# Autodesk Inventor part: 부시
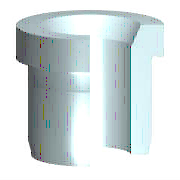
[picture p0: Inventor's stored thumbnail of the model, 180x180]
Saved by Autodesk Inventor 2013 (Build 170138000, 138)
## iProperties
IsCustomPart: 1
Created: 2009-02
Part Number: 부시
Material: 강, 연강
Description: 압력 맞춤 부시 - 머리 있는 유형
Document SubType Name: Modeling
Standard: ISO 4247
Designer: KYOUNG IL JANG
Standard Revision: 1판 1977-12-15
Standards Organization: ISO
Language: ko-KR
Size Designation: 15
Categories: <MemberInstance><Categories><Category DisplayName="기타 부품" InternalName="5aa15e00-363f-49f2-933f-16f664388e3f" Mnemonic="OTHER"><Category DisplayName="드릴 부싱" Int
Density: 7.86 g/cm^3
Mass: 62.5871 g
Surface Area: 38.4072 cm^2
Volume: 7.96273 cm^3
Author: KYOUNG IL JANG
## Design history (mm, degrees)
revolve "본체" stored, may be unused: angle "d12" = 90 deg
body "Solid1"
chamfer "모따기1" distance "d13" = 2 (= KAH); stored, may be unused: angle "d14" = 30 deg (= SEWI), second distance "d19" = 2 (= KAH)
chamfer "모따기2" distance "d15" = 1.5 (= PHH); stored, may be unused: angle "d16" = 15 deg (= ANG), second distance "d20" = 1.5 (= PHH)
sketch "스케치1"
  geometry: L1 (2.5, 11)-(24, 11); L2 (24, 11)-(24, 6); L3 (24, 6)-(-4, 6); L4 (-4, 6)-(-4, 13); L5 (-4, 13)-(0, 13); L6 (0, 13)-(0, 12.304); L7 (-2.619, 0)-(24, 0); L8 (0, 12.304)-(-0.187, 11.425); L9 (2.5, 11)-(1.457, 10.72); L10 (0.4, 10.7)-(1.301, 10.7); L11 (-6.4, 0)-(10.4, 0) reference; L12 (0, -2.2)-(0, 13.2) reference; A1 r 0.6 centre (1.301, 11.3) between (1.301, 10.7) and (1.457, 10.72); A2 r 0.6 centre (0.4, 11.3) between (-0.187, 11.425) and (0.4, 10.7)
  constraints: 20 end point, 5 parallel, 4 point on circle, 4 tangent, 2 centre point, 2 collinear, 2 perpendicular, 1 horizontal, 1 point on line
  dimensions: "d0" = 15 deg angle of L1 L9; "d1" = 12 deg angle of L6 L8; "d2" = 0.6 radius of A2 (= FSRR); "d3" = 0.6 radius of A1 (= FSRR); "d4" = 0.3 distance between parallel lines of L1 L10 (= FST1); "d5" = 0.2 distance edge to line of A2 L6 (= FST2); "d6" = 2.5 distance from line of L1.start L6 (= FSB); "d7" = 12 diameter of L3 L7 (= NND); "d8" = 22 diameter of L1 L7 (= SD2); "d9" = 28 distance between parallel lines of L2 L4 (= NLG); "d10" = 4 distance of L4.end L5.end (= KOH); "d11" = 26 diameter of L5 L7 (= KOD)
other parameters: "NLG" = 28 [user parameter; used in 1 equation term], "NND" = 12 [user parameter; used in 1 equation term], "KOH" = 4 [user parameter; used in 1 equation term], "KOD" = 26 [user parameter; used in 1 equation term], "KAH" = 2 [user parameter; used in 2 equation terms], "SEWI" = 30 deg [user parameter; used in 1 equation term], "ANG" = 15 deg [user parameter; used in 1 equation term], "PHH" = 1.5 [user parameter; used in 2 equation terms], "FST1" = 0.3 [user parameter; used in 1 equation term], "FST2" = 0.2 [user parameter; used in 1 equation term], "FSB" = 2.5 [user parameter; used in 1 equation term], "FSRR" = 0.6 [user parameter; used in 2 equation terms], "SD2" = 22 [user parameter; used in 1 equation term], "d17" = 0, "d18" = 0, "NNDMIN" = 12 [user parameter], "FSH" = 2.1 [user parameter], "NNDMAX" = 15 [user parameter]
